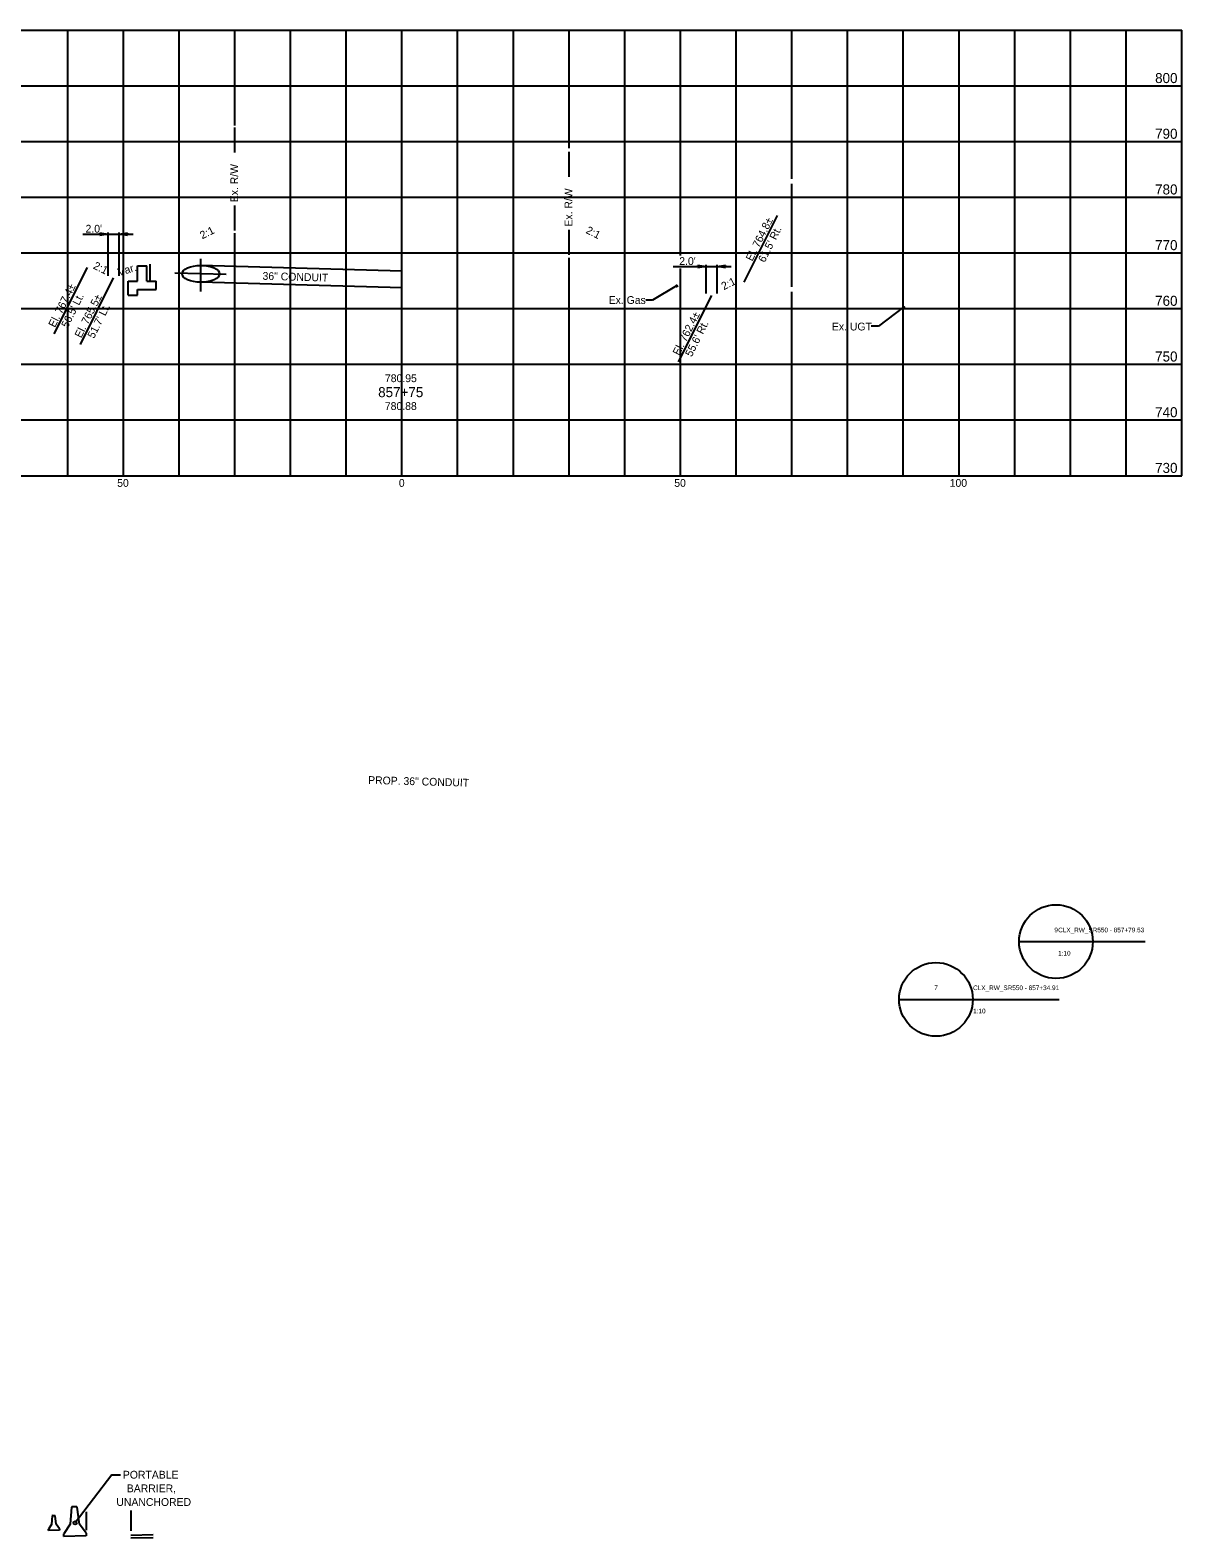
# Model space of a CAD drawing. Extents: x -1395 to 1843, y -1176 to 1887.
# Drawn here: x -1034 to -620, y 1346 to 1887 of the extents above; entities that cross this region are included whole.
import ezdxf

# ---------------------------------------------------------------- set-up
doc = ezdxf.new("R2010")
doc.units = 0
for name, color, linetype in [('BD_X_Building', 7, 'Continuous'), ('GE_X_Alignment', 7, 'Continuous'), ('MT_P_Temp_Road', 7, 'Continuous'), ('PV_X_Driveway', 7, 'Continuous'), ('PV_X_EOP', 7, 'Continuous'), ('PV_X_Shoulder', 7, 'Continuous'), ('RD_X_Concrete_Pad', 7, 'Continuous'), ('RD_X_GR_Lt', 7, 'Continuous'), ('RW_P_Esmt_SH', 7, 'Continuous'), ('RW_P_Esmt_TMP', 7, 'Continuous'), ('SH_Data', 7, 'Continuous'), ('SH_Major_Grid_Line', 7, 'Continuous'), ('SV_X_Break_Lines', 7, 'Continuous'), ('SV_X_Random_Point', 7, 'Continuous'), ('SV_X_Top_of_Bank', 7, 'Continuous'), ('XS_P_Headwall', 7, 'Continuous')]:
    doc.layers.add(name, color=color, linetype=linetype)

msp = doc.modelspace()

# ---------------------------------------------------------------- linework, layer by layer
at = {"layer": 'BD_X_Building'}
msp.add_line((-997.52, 1345.95), (-989.5, 1346.12), dxfattribs=at)
at = {"layer": 'GE_X_Alignment'}
for p, q in [((-1180.15, 1887.4), (-620.15, 1887.4)), ((-777.23, 1796.95), (-765.31, 1820.81)), ((-1024.99, 1778.33), (-1013.07, 1802.19)), ((-1015.58, 1774.54), (-1003.65, 1798.4)), ((-801.52, 1795.53), (-810.24, 1790.48)), ((-810.24, 1790.48), (-812.63, 1790.48)), ((-800.85, 1768.24), (-788.93, 1792.1)), ((-720.07, 1787.92), (-729.09, 1781.04)), ((-729.09, 1781.04), (-731.7, 1781.04))]:
    msp.add_line(p, q, dxfattribs=at)
at = {"layer": 'MT_P_Temp_Road'}
for p, q in [((-990.54, 1797.4), (-990.54, 1803.4)), ((-900.15, 1800.88), (-972.35, 1802.89)), ((-900.15, 1794.88), (-972.35, 1796.89))]:
    msp.add_line(p, q, dxfattribs=at)
msp.add_ellipse((-972.35, 1799.89), major_axis=(-6.72, 0), ratio=0.446429, dxfattribs=at)
at = {"layer": 'PV_X_Driveway'}
msp.add_line((-997.52, 1346.95), (-989.52, 1347.12), dxfattribs=at)
at = {"layer": 'PV_X_EOP'}
for p, q in [((-678.56, 1560.08), (-652.1, 1560.08)), ((-665.21, 1560.08), (-633.29, 1560.08)), ((-721.66, 1539.32), (-695.2, 1539.32)), ((-708.32, 1539.32), (-664.14, 1539.32))]:
    msp.add_line(p, q, dxfattribs=at)
for centre in [(-665.33, 1560.08), (-708.43, 1539.32)]:
    msp.add_circle(centre, 13.23, dxfattribs=at)
at = {"layer": 'PV_X_Shoulder'}
msp.add_circle((-801.52, 1795.53), 0.25, dxfattribs=at)
at = {"layer": 'RD_X_Concrete_Pad'}
msp.add_circle((-1017.5, 1351.32), 0.597, dxfattribs=at)
at = {"layer": 'RD_X_GR_Lt'}
msp.add_circle((-720.07, 1787.92), 0.25, dxfattribs=at)
at = {"layer": 'RW_P_Esmt_SH'}
for p, q in [((-995.05, 1797.24), (-995.05, 1802.74)), ((-995.05, 1802.74), (-991.71, 1802.74)), ((-991.71, 1797.24), (-991.71, 1802.74)), ((-998.41, 1792.24), (-998.41, 1797.24)), ((-998.41, 1797.24), (-995.05, 1797.24)), ((-998.41, 1792.24), (-995.05, 1792.24)), ((-995.05, 1794.24), (-988.35, 1794.24)), ((-995.05, 1792.24), (-995.05, 1794.24)), ((-991.71, 1797.24), (-988.35, 1797.24)), ((-990.54, 1797.24), (-990.54, 1797.4)), ((-988.35, 1794.24), (-988.35, 1797.24))]:
    msp.add_line(p, q, dxfattribs=at)
at = {"layer": 'RW_P_Esmt_TMP'}
for p, q in [((-1020.15, 1727.4), (-1020.15, 1887.4)), ((-1000.15, 1727.4), (-1000.15, 1887.4)), ((-980.15, 1727.4), (-980.15, 1887.4)), ((-960.15, 1853.21), (-960.15, 1887.4)), ((-940.15, 1727.4), (-940.15, 1887.4)), ((-920.15, 1727.4), (-920.15, 1887.4)), ((-900.15, 1727.4), (-900.15, 1887.4)), ((-880.15, 1727.4), (-880.15, 1887.4)), ((-860.15, 1727.4), (-860.15, 1887.4)), ((-840.15, 1844.98), (-840.15, 1887.4)), ((-820.15, 1727.4), (-820.15, 1887.4)), ((-800.15, 1806.5), (-800.15, 1887.4)), ((-780.15, 1727.4), (-780.15, 1887.4)), ((-760.15, 1834.05), (-760.15, 1887.4)), ((-740.15, 1727.4), (-740.15, 1887.4)), ((-720.15, 1727.4), (-720.15, 1887.4)), ((-700.15, 1727.4), (-700.15, 1887.4)), ((-680.15, 1727.4), (-680.15, 1887.4)), ((-660.15, 1727.4), (-660.15, 1887.4)), ((-640.15, 1727.4), (-640.15, 1887.4)), ((-620.15, 1727.4), (-620.15, 1887.4)), ((-1180.15, 1867.4), (-620.15, 1867.4)), ((-1180.15, 1847.4), (-620.15, 1847.4)), ((-1180.15, 1827.4), (-620.15, 1827.4)), ((-960.15, 1727.4), (-960.15, 1814.45)), ((-1180.15, 1807.4), (-620.15, 1807.4)), ((-972.35, 1793.51), (-972.35, 1805.26)), ((-840.15, 1727.4), (-840.15, 1805.6)), ((-963.26, 1799.64), (-981.74, 1800.16)), ((-800.15, 1727.4), (-800.15, 1801.83)), ((-760.15, 1727.4), (-760.15, 1793.46)), ((-1180.15, 1787.4), (-620.15, 1787.4)), ((-1180.15, 1767.4), (-620.15, 1767.4)), ((-1180.15, 1747.4), (-620.15, 1747.4)), ((-1180.15, 1727.4), (-620.15, 1727.4))]:
    msp.add_line(p, q, dxfattribs=at)
at = {"layer": 'SH_Major_Grid_Line'}
for p, q in [((-1004.28, 1368.61), (-1017.5, 1351.32)), ((-1004.28, 1368.61), (-1001.17, 1368.61)), ((-1013.52, 1355.27), (-1013.52, 1348.72)), ((-997.52, 1355.79), (-997.52, 1348.49))]:
    msp.add_line(p, q, dxfattribs=at)
at = {"layer": 'SV_X_Break_Lines'}
msp.add_line((-760.15, 1795.27), (-760.15, 1832.19), dxfattribs=at)
at = {"layer": 'SV_X_Random_Point'}
for p, q in [((-1014.71, 1814.11), (-1005.65, 1814.11)), ((-1005.65, 1814.11), (-1008.62, 1813.62)), ((-1008.61, 1814.61), (-1008.61, 1814.61)), ((-1008.61, 1814.61), (-1005.65, 1814.11)), ((-1005.65, 1799.13), (-1005.65, 1814.71)), ((-1005.65, 1814.11), (-1001.65, 1814.11)), ((-1001.65, 1799.13), (-1001.65, 1814.71)), ((-1001.65, 1814.11), (-998.68, 1814.61)), ((-998.69, 1813.62), (-1001.65, 1814.11)), ((-1001.65, 1814.11), (-996.64, 1814.11)), ((-998.68, 1814.61), (-998.68, 1814.61)), ((-1008.62, 1813.62), (-1008.61, 1813.62)), ((-998.69, 1813.62), (-998.69, 1813.62)), ((-790.93, 1792.83), (-790.93, 1803.14)), ((-786.93, 1792.83), (-786.93, 1803.14)), ((-802.75, 1802.54), (-790.93, 1802.54)), ((-790.93, 1802.54), (-793.89, 1802.05)), ((-793.89, 1802.05), (-793.89, 1802.05)), ((-793.88, 1803.04), (-793.88, 1803.04)), ((-793.88, 1803.04), (-790.93, 1802.54)), ((-790.93, 1802.54), (-786.93, 1802.54)), ((-786.93, 1802.54), (-783.96, 1803.04)), ((-783.97, 1802.05), (-786.93, 1802.54)), ((-786.93, 1802.54), (-781.92, 1802.54)), ((-783.97, 1802.05), (-783.97, 1802.05)), ((-783.96, 1803.04), (-783.96, 1803.04))]:
    msp.add_line(p, q, dxfattribs=at)
for centre, start, end in [((-1009.36, 1814.12), 326.178, 32.8588), ((-997.93, 1814.11), 146.178, 212.8588), ((-794.64, 1802.55), 326.178, 32.8588), ((-783.21, 1802.53), 146.178, 212.8588)]:
    msp.add_arc(centre, 0.9, start, end, dxfattribs=at)
at = {"layer": 'SV_X_Top_of_Bank'}
for p, q in [((-960.15, 1843.47), (-960.15, 1852.39)), ((-840.15, 1834.72), (-840.15, 1843.65)), ((-960.15, 1815.48), (-960.15, 1824.41)), ((-840.15, 1806.74), (-840.15, 1815.67))]:
    msp.add_line(p, q, dxfattribs=at)
at = {"layer": 'XS_P_Headwall'}
for p, q in [((-1025.67, 1353.83), (-1025.93, 1350.78)), ((-1025.54, 1353.96), (-1025.67, 1353.83)), ((-1025.54, 1353.96), (-1024.79, 1353.97)), ((-1024.65, 1353.85), (-1024.79, 1353.97)), ((-1024.26, 1350.82), (-1024.65, 1353.85)), ((-1018.76, 1356.93), (-1019.27, 1350.83)), ((-1018.49, 1357.18), (-1018.76, 1356.93)), ((-1018.49, 1357.18), (-1016.99, 1357.21)), ((-1016.71, 1356.97), (-1016.99, 1357.21)), ((-1015.94, 1350.9), (-1016.71, 1356.97)), ((-1025.93, 1350.78), (-1027.06, 1349.09)), ((-1027.05, 1348.59), (-1027.06, 1349.09)), ((-1023.05, 1348.68), (-1027.05, 1348.59)), ((-1023.06, 1349.18), (-1024.26, 1350.82)), ((-1023.06, 1349.18), (-1023.05, 1348.68)), ((-1019.27, 1350.83), (-1021.54, 1347.45)), ((-1013.54, 1347.61), (-1015.94, 1350.9)), ((-1021.52, 1346.45), (-1021.54, 1347.45)), ((-1013.52, 1346.62), (-1021.52, 1346.45)), ((-1013.54, 1347.61), (-1013.52, 1346.62))]:
    msp.add_line(p, q, dxfattribs=at)

# ---------------------------------------------------------------- texts
at = {"layer": 'PV_X_EOP'}
for s, height, p in [('9', 1.67, (-665.93, 1563.41)), ('CLX_RW_SR550 - 857+79.53', 1.6667, (-664.56, 1563.41)), ('1:10', 1.667, (-664.56, 1555.08)), ('7', 1.67, (-709.03, 1542.65)), ('CLX_RW_SR550 - 857+34.91', 1.6667, (-695.09, 1542.65)), ('1:10', 1.667, (-695.09, 1534.32))]:
    msp.add_text(s, height=height, dxfattribs=at).set_placement(p)
at = {"layer": 'SH_Data'}
for s, height, p in [('800', 3.6, (-629.74, 1868.4)), ('790', 3.6, (-629.74, 1848.4)), ('780', 3.6, (-629.74, 1828.4)), ("2.0'", 2.8, (-1013.74, 1814.69)), ('770', 3.6, (-629.74, 1808.4)), ("2.0'", 2.8, (-800.59, 1803.06)), ('Ex. Gas', 2.8, (-825.92, 1789.08)), ('760', 3.6, (-629.74, 1788.4)), ('Ex. UGT', 2.8, (-745.78, 1779.56)), ('750', 3.6, (-629.74, 1768.4)), ('780.95', 2.8, (-906.25, 1761)), ('857+75', 3.6, (-908.68, 1755.6)), ('780.88', 2.8, (-906.28, 1751)), ('740', 3.6, (-629.74, 1748.4)), ('730', 3.6, (-629.74, 1728.4)), ('50', 2.8, (-1002.38, 1723.4)), ('0', 2.8, (-901.26, 1723.4)), ('50', 2.8, (-802.38, 1723.4)), ('100', 2.8, (-703.5, 1723.4)), ('PORTABLE', 2.8, (-1000.34, 1367.22)), ('BARRIER,', 2.8, (-998.92, 1362.32)), ('UNANCHORED', 2.8, (-1002.68, 1357.42))]:
    msp.add_text(s, height=height, dxfattribs=at).set_placement(p)
for s, rotation, p in [('El. 764.8±', 63.4349, (-774.38, 1804.21)), ('2:1', 26.5651, (-971.83, 1812.26)), ('2:1', 333.4349, (-834.36, 1814.64)), ("61.5' Rt.", 63.4349, (-769.92, 1803.75)), ('2:1', 333.4349, (-1011.24, 1801.92)), ('Var.', 16.8589, (-1001.74, 1799.05)), ('36" CONDUIT', 358.3999, (-950.23, 1797.76)), ('2:1', 26.5651, (-784.63, 1793.98)), ('El. 767.4±', 63.4349, (-1024.73, 1780.43)), ('El. 765.5±', 63.4349, (-1015.31, 1776.64)), ("56.5' Lt.", 63.4349, (-1020.12, 1780.25)), ("51.7' Lt.", 63.4349, (-1010.71, 1776.46)), ('El. 762.4±', 63.4349, (-800.59, 1770.34)), ("55.6' Rt.", 63.4349, (-796.12, 1769.88)), ('PROP. 36" CONDUIT', 358.3999, (-912.32, 1616.72))]:
    msp.add_text(s, height=2.8, rotation=rotation, dxfattribs=at).set_placement(p)
at = {"layer": 'SV_X_Top_of_Bank'}
for p in [(-958.96, 1825.6), (-838.96, 1816.86)]:
    msp.add_text('Ex. R/W', height=2.8, rotation=90, dxfattribs=at).set_placement(p)

doc.saveas('drawing.dxf')
